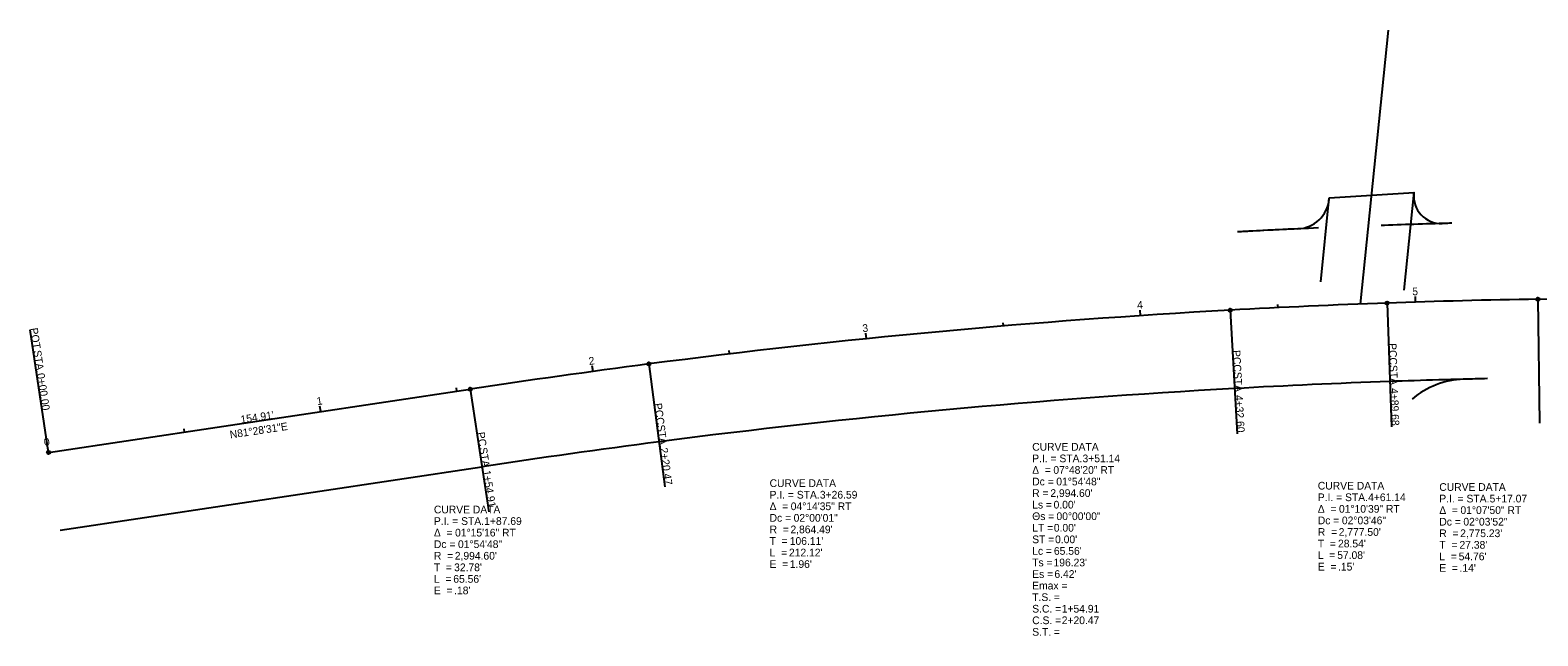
# Model space of a CAD drawing. Extents: x 1369241 to 1370511, y 405374 to 406419.
# Drawn here: x 1369241 to 1369789, y 405785 to 406005 of the extents above; entities that cross this region are included whole.
import ezdxf

# ---------------------------------------------------------------- set-up
doc = ezdxf.new("R2010")
doc.units = 0
for name, color, linetype in [('Default', 7, 'Continuous'), ('DT_P_Contour_Major', 7, 'Continuous'), ('GE_P_Alignment_100_Bearings', 7, 'Continuous'), ('GE_P_Alignment_100_Cardinal_Points', 7, 'Continuous'), ('GE_P_Alignment_100_Curve_Data', 7, 'Continuous'), ('GE_P_Alignment_100_Distances', 7, 'Continuous'), ('GE_P_Alignment_100_Stations', 7, 'Continuous'), ('SG_P_Poles', 7, 'Continuous')]:
    doc.layers.add(name, color=color, linetype=linetype)

msp = doc.modelspace()

# ---------------------------------------------------------------- linework, layer by layer
at = {"layer": 'Default'}
msp.add_line((1369712.8, 405944.06), (1369743.57, 405946), dxfattribs=at)
at = {"layer": 'DT_P_Contour_Major'}
for p, q in [((1369709.7, 405913.56), (1369712.8, 405944.06)), ((1369712.75, 405943.54), (1369712.8, 405944.06)), ((1369712.75, 405943.54), (1369712.8, 405944.06)), ((1369739.96, 405910.48), (1369743.57, 405946.05)), ((1369743.54, 405945.71), (1369743.57, 405946.05)), ((1369743.54, 405945.71), (1369743.57, 405946.05)), ((1369734.8, 405877.32), (1369734.82, 405877.32)), ((1369734.82, 405877.32), (1369734.83, 405877.32)), ((1369678.36, 405874.77), (1369678.36, 405874.77)), ((1369678.36, 405874.77), (1369678.36, 405874.77)), ((1369251.72, 405823.37), (1369404.96, 405846.34)), ((1369404.96, 405846.34), (1369404.99, 405846.35))]:
    msp.add_line(p, q, dxfattribs=at)
for centre, radius, start, end in [((1369700.81, 405944.75), 12, 272.638, 354.1946), ((1369700.81, 405944.75), 12, 272.638, 354.1946), ((1369753.49, 405944.7), 10, 174.1946, 271.6194), ((1369753.49, 405944.7), 10, 174.1946, 271.6194), ((1369830.5, 403129.99), 2805.75, 92.48417, 93.08523), ((1369830.5, 403129.99), 2805.75, 92.63802, 93.08523), ((1369830.5, 403129.99), 2805.75, 92.63802, 93.08523), ((1369830.5, 403129.99), 2805.75, 91.99516, 92.01847), ((1369833, 403132.35), 2803.48, 91.54611, 92.04788), ((1369833, 403132.35), 2803.48, 91.54611, 91.61942), ((1369833, 403132.35), 2803.48, 91.54611, 91.61942), ((1369830.5, 403129.99), 2749, 91.99489, 93.17247), ((1369833, 403132.35), 2746.73, 91.30944, 92.04814), ((1369762.4, 405848.16), 30, 91.4891, 130.4919), ((1369762.4, 405848.16), 30, 91.4891, 130.4919), ((1369833, 403132.35), 2746.73, 91.30944, 91.48909), ((1369833, 403132.35), 2746.73, 91.30944, 91.48909), ((1369834.84, 403043.1), 2835.99, 93.16294, 97.40579), ((1369852.34, 402914.17), 2966.1, 97.42004, 98.67441)]:
    msp.add_arc(centre, radius, start, end, dxfattribs=at)
at = {"layer": 'GE_P_Alignment_100_Cardinal_Points'}
for p, q in [((1369676.79, 405903.23), (1369679.28, 405858.3)), ((1369733.81, 405905.8), (1369735.42, 405860.83)), ((1369788.56, 405907.22), (1369789.17, 405862.23)), ((1369247.5, 405851.56), (1369240.83, 405896.06)), ((1369465.61, 405883.7), (1369471.41, 405839.07)), ((1369400.7, 405874.52), (1369407.48, 405830.04))]:
    msp.add_line(p, q, dxfattribs=at)
for centre in [(1369788.56, 405907.22), (1369676.79, 405903.23), (1369733.81, 405905.8), (1369465.61, 405883.7), (1369400.7, 405874.52), (1369247.5, 405851.56)]:
    msp.add_circle(centre, 0.6, dxfattribs=at)
at = {"layer": 'GE_P_Alignment_100_Stations'}
for p, q in [((1369744.12, 405906.15), (1369744.06, 405908.15)), ((1369644.25, 405901.25), (1369644.12, 405903.24)), ((1369694.16, 405904.14), (1369694.11, 405905.34)), ((1369594.39, 405897.49), (1369594.29, 405898.68)), ((1369544.61, 405892.85), (1369544.4, 405894.84)), ((1369494.91, 405887.35), (1369494.77, 405888.55)), ((1369445.32, 405880.99), (1369445.05, 405882.97)), ((1369395.84, 405873.79), (1369395.66, 405874.98)), ((1369346.39, 405866.38), (1369346.1, 405868.36)), ((1369296.94, 405858.97), (1369296.77, 405860.16)), ((1369247.5, 405851.56), (1369247.2, 405853.54))]:
    msp.add_line(p, q, dxfattribs=at)
at = {"layer": 'SG_P_Poles'}
for p, q in [((1369724.14, 405905.45), (1369734.25, 406004.94)), ((1369788.56, 405907.22), (1370023.59, 405910.4)), ((1369788.56, 405907.22), (1370023.59, 405910.4)), ((1369247.5, 405851.56), (1369400.7, 405874.52)), ((1369247.5, 405851.56), (1369400.7, 405874.52))]:
    msp.add_line(p, q, dxfattribs=at)
for centre, radius, start, end in [((1369834.84, 403043.1), 2864.49, 93.16294, 97.40586), ((1369834.84, 403043.1), 2864.49, 93.16294, 97.40586), ((1369830.5, 403129.99), 2777.5, 91.99489, 93.17247), ((1369830.5, 403129.99), 2777.5, 91.99489, 93.17247), ((1369833, 403132.35), 2775.23, 90.9175, 92.04814), ((1369833, 403132.35), 2775.23, 90.9175, 92.04814), ((1369852.34, 402914.17), 2994.6, 97.41997, 98.67441), ((1369852.34, 402914.17), 2994.6, 97.41997, 98.67441)]:
    msp.add_arc(centre, radius, start, end, dxfattribs=at)

# ---------------------------------------------------------------- texts
at = {"layer": 'GE_P_Alignment_100_Bearings'}
msp.add_text('N81°28\'31"E', height=2.8, rotation=8.5247, dxfattribs=at).set_placement((1369313.57, 405856.61))
at = {"layer": 'GE_P_Alignment_100_Cardinal_Points'}
for s, rotation, p in [('POT', 278.5247, (1369240.78, 405896.62)), (' STA. ', 278.5247, (1369241.85, 405889.5)), ('PCC', 273.1725, (1369677.64, 405888.66)), ('PCC', 272.0481, (1369734.38, 405891.21)), (' STA. ', 273.1725, (1369678.02, 405881.78)), (' STA. ', 272.0481, (1369734.62, 405884.33)), ('0+00.00', 278.5247, (1369243.25, 405880.16)), ('4+32.60', 273.1725, (1369678.54, 405872.35)), ('4+89.68', 272.0481, (1369734.96, 405874.88)), ('PCC', 277.4059, (1369467.53, 405869.3)), ('PC', 278.6744, (1369403.14, 405858.77)), (' STA. ', 277.4059, (1369468.41, 405862.47)), (' STA. ', 278.6744, (1369403.83, 405854.24)), ('2+20.47', 277.4059, (1369469.63, 405853.1)), ('1+54.91', 278.6744, (1369405.26, 405844.89))]:
    msp.add_text(s, height=2.8, rotation=rotation, dxfattribs=at).set_placement(p)
at = {"layer": 'GE_P_Alignment_100_Curve_Data'}
for s, p in [('CURVE DATA', (1369604.87, 405852.2)), ('P.I. = STA. ', (1369604.87, 405848)), ('3+51.14', (1369623.14, 405848)), ('Δ  = ', (1369604.87, 405843.8)), ('Dc = ', (1369604.87, 405839.6)), ('07°48\'20" RT', (1369612.55, 405843.8)), ('01°54\'48"', (1369613.61, 405839.6)), ('CURVE DATA', (1369509.46, 405839.01)), ('P.I. = STA. ', (1369509.46, 405834.81)), ('3+26.59', (1369527.72, 405834.81)), ('R = ', (1369604.87, 405835.4)), ("2,994.60'", (1369611.46, 405835.4)), ('CURVE DATA', (1369708.63, 405838.08)), ('P.I. = STA. ', (1369708.63, 405833.88)), ('4+61.14', (1369726.9, 405833.88)), ('CURVE DATA', (1369752.76, 405837.61)), ('CURVE DATA', (1369387.51, 405829.44)), ('Δ  = ', (1369509.46, 405830.61)), ('04°14\'35" RT', (1369517.13, 405830.61)), ('Ls = ', (1369604.87, 405831.2)), ("0.00'", (1369612.63, 405831.2)), ('Δ  = ', (1369708.63, 405829.68)), ('01°10\'39" RT', (1369716.31, 405829.68)), ('Δ  = ', (1369752.76, 405829.21)), ('P.I. = STA. ', (1369752.76, 405833.41)), ('01°07\'50" RT', (1369760.44, 405829.21)), ('5+17.07', (1369771.03, 405833.41)), ('P.I. = STA. ', (1369387.51, 405825.24)), ('1+87.69', (1369405.78, 405825.24)), ('Dc = ', (1369509.46, 405826.41)), ('02°00\'01"', (1369518.19, 405826.41)), ('Θs = ', (1369604.87, 405827)), ('00°00\'00"', (1369613.67, 405827)), ('Dc = ', (1369708.63, 405825.48)), ('02°03\'46"', (1369717.37, 405825.48)), ('Dc = ', (1369752.76, 405825.01)), ('02°03\'52"', (1369761.5, 405825.01)), ('Δ  = ', (1369387.51, 405821.04)), ('01°15\'16" RT', (1369395.19, 405821.04)), ('T  = ', (1369509.46, 405818.01)), ('R  = ', (1369509.46, 405822.21)), ("106.11'", (1369516.79, 405818.01)), ("2,864.49'", (1369517.04, 405822.21)), ('ST = ', (1369604.87, 405818.6)), ('LT = ', (1369604.87, 405822.8)), ("0.00'", (1369612.72, 405822.8)), ("0.00'", (1369613.18, 405818.6)), ('R  = ', (1369708.63, 405821.28)), ("2,777.50'", (1369716.21, 405821.28)), ('R  = ', (1369752.76, 405820.81)), ("2,775.23'", (1369760.34, 405820.81)), ('Dc = ', (1369387.51, 405816.84)), ('R  = ', (1369387.51, 405812.64)), ("2,994.60'", (1369395.09, 405812.64)), ('01°54\'48"', (1369396.25, 405816.84)), ('L  = ', (1369509.46, 405813.81)), ("212.12'", (1369516.5, 405813.81)), ('Lc = ', (1369604.87, 405814.4)), ("65.56'", (1369612.75, 405814.4)), ('T  = ', (1369708.63, 405817.08)), ('L  = ', (1369708.63, 405812.88)), ("57.08'", (1369715.67, 405812.88)), ("28.54'", (1369715.97, 405817.08)), ('T  = ', (1369752.76, 405816.61)), ('L  = ', (1369752.76, 405812.41)), ("54.76'", (1369759.8, 405812.41)), ("27.38'", (1369760.1, 405816.61)), ('T  = ', (1369387.51, 405808.44)), ("32.78'", (1369394.85, 405808.44)), ('E  = ', (1369509.46, 405809.61)), ("1.96'", (1369516.8, 405809.61)), ('Ts = ', (1369604.87, 405810.2)), ("196.23'", (1369612.61, 405810.2)), ('E  = ', (1369708.63, 405808.68)), (".15'", (1369715.97, 405808.68)), ('E  = ', (1369752.76, 405808.21)), (".14'", (1369760.1, 405808.21)), ('L  = ', (1369387.51, 405804.24)), ("65.56'", (1369394.55, 405804.24)), ('Es = ', (1369604.87, 405806)), ('Emax = ', (1369604.87, 405801.8)), ("6.42'", (1369612.93, 405806)), ('E  = ', (1369387.51, 405800.04)), (".18'", (1369394.85, 405800.04)), ('T.S. = ', (1369604.87, 405797.6)), ('S.C. = ', (1369604.87, 405793.4)), ('1+54.91', (1369615.59, 405793.4)), ('S.T. = ', (1369604.87, 405785)), ('C.S. = ', (1369604.87, 405789.2)), ('2+20.47', (1369615.59, 405789.2))]:
    msp.add_text(s, height=2.8, dxfattribs=at).set_placement(p)
at = {"layer": 'GE_P_Alignment_100_Distances'}
msp.add_text("154.91'", height=2.8, rotation=8.5247, dxfattribs=at).set_placement((1369317.48, 405862.09))
at = {"layer": 'GE_P_Alignment_100_Stations'}
for s, rotation, p in [('5', 1.8352, (1369742.97, 405908.62)), ('4', 3.815, (1369643.05, 405903.67)), ('3', 5.8152, (1369543.32, 405895.24)), ('2', 7.8117, (1369443.94, 405883.32)), ('1', 8.5247, (1369345.12, 405868.72)), ('0', 8.5247, (1369246.03, 405853.87))]:
    msp.add_text(s, height=2.8, rotation=rotation, dxfattribs=at).set_placement(p)

doc.saveas('drawing.dxf')
